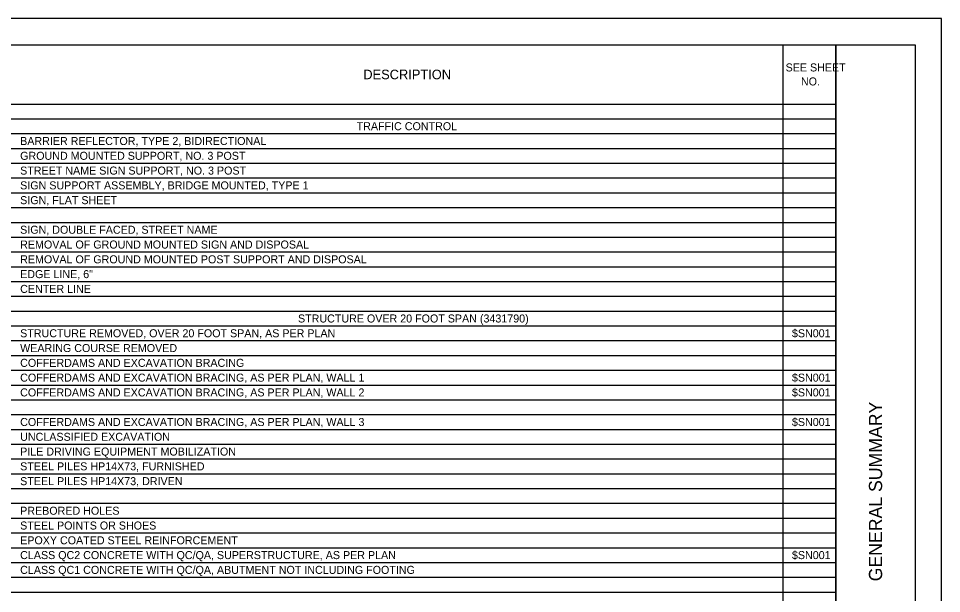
# Model space of a CAD drawing. Extents: x 0 to 34, y 0 to 22.
# Drawn here: x 16.52 to 34, y 11.11 to 22 of the extents above; entities that cross this region are included whole.
import ezdxf

# ---------------------------------------------------------------- set-up
doc = ezdxf.new("R2010")
doc.units = 0
for name, color, linetype in [('SH_Border', 7, 'Continuous'), ('SH_Cut_Line', 7, 'Continuous'), ('SH_Data', 7, 'Continuous'), ('SH_Text', 7, 'Continuous')]:
    doc.layers.add(name, color=color, linetype=linetype)

msp = doc.modelspace()

# ---------------------------------------------------------------- linework, layer by layer
at = {"layer": 'SH_Border'}
msp.add_line((32, 0.5), (32, 21.5), dxfattribs=at)
msp.add_lwpolyline([(1.5, 21.5), (33.5, 21.5), (33.5, 0.5), (1.5, 0.5)], close=True, dxfattribs=at)
at = {"layer": 'SH_Cut_Line'}
msp.add_lwpolyline([(0, 0), (34, 0), (34, 22), (0, 22)], close=True, dxfattribs=at)
at = {"layer": 'SH_Text'}
for p, q in [((1.5, 21.5), (32, 21.5)), ((30.995, 21.5), (30.995, 0.5)), ((32, 21.5), (32, 0.5)), ((1.5, 20.38), (32, 20.38)), ((1.5, 20.1), (32, 20.1)), ((1.5, 19.82), (32, 19.82)), ((1.5, 19.54), (32, 19.54)), ((1.5, 19.26), (32, 19.26)), ((1.5, 18.98), (32, 18.98)), ((1.5, 18.7), (32, 18.7)), ((1.5, 18.42), (32, 18.42)), ((1.5, 18.14), (32, 18.14)), ((1.5, 17.86), (32, 17.86)), ((1.5, 17.58), (32, 17.58)), ((1.5, 17.3), (32, 17.3)), ((1.5, 17.02), (32, 17.02)), ((1.5, 16.74), (32, 16.74)), ((1.5, 16.46), (32, 16.46)), ((1.5, 16.18), (32, 16.18)), ((1.5, 15.9), (32, 15.9)), ((1.5, 15.62), (32, 15.62)), ((1.5, 15.34), (32, 15.34)), ((1.5, 15.06), (32, 15.06)), ((1.5, 14.78), (32, 14.78)), ((1.5, 14.5), (32, 14.5)), ((1.5, 14.22), (32, 14.22)), ((1.5, 13.94), (32, 13.94)), ((1.5, 13.66), (32, 13.66)), ((1.5, 13.38), (32, 13.38)), ((1.5, 13.1), (32, 13.1)), ((1.5, 12.82), (32, 12.82)), ((1.5, 12.54), (32, 12.54)), ((1.5, 12.26), (32, 12.26)), ((1.5, 11.98), (32, 11.98)), ((1.5, 11.7), (32, 11.7)), ((1.5, 11.42), (32, 11.42)), ((1.5, 11.14), (32, 11.14))]:
    msp.add_line(p, q, dxfattribs=at)

# ---------------------------------------------------------------- texts
at = {"layer": 'SH_Data'}
msp.add_text('GENERAL SUMMARY', height=0.25, rotation=90, dxfattribs=at).set_placement((32.875, 11.344))
at = {"layer": 'SH_Text'}
for s, height, p in [('DESCRIPTION', 0.18184, (23.05, 20.849)), ('SEE SHEET ', 0.1515, (31.047, 20.997)), ('NO.', 0.1515, (31.338, 20.732)), ('TRAFFIC CONTROL', 0.15153, (22.924, 19.884)), ('BARRIER REFLECTOR, TYPE 2, BIDIRECTIONAL', 0.15153, (16.552, 19.604)), ('GROUND MOUNTED SUPPORT, NO. 3 POST', 0.15153, (16.552, 19.324)), ('STREET NAME SIGN SUPPORT, NO. 3 POST', 0.15153, (16.552, 19.044)), ('SIGN SUPPORT ASSEMBLY, BRIDGE MOUNTED, TYPE 1', 0.15153, (16.552, 18.764)), ('SIGN, FLAT SHEET', 0.15153, (16.552, 18.484)), ('SIGN, DOUBLE FACED, STREET NAME', 0.15153, (16.552, 17.924)), ('REMOVAL OF GROUND MOUNTED SIGN AND DISPOSAL', 0.15153, (16.552, 17.644)), ('REMOVAL OF GROUND MOUNTED POST SUPPORT AND DISPOSAL', 0.15153, (16.552, 17.364)), ('EDGE LINE, 6"', 0.15153, (16.552, 17.084)), ('CENTER LINE', 0.15153, (16.552, 16.804)), ('STRUCTURE OVER 20 FOOT SPAN (3431790)', 0.15153, (21.813, 16.244)), ('STRUCTURE REMOVED, OVER 20 FOOT SPAN, AS PER PLAN', 0.15153, (16.552, 15.964)), ('$SN001', 0.1515, (31.167, 15.964)), ('WEARING COURSE REMOVED', 0.15153, (16.552, 15.684)), ('COFFERDAMS AND EXCAVATION BRACING', 0.15153, (16.552, 15.404)), ('COFFERDAMS AND EXCAVATION BRACING, AS PER PLAN, WALL 1', 0.15153, (16.552, 15.124)), ('$SN001', 0.1515, (31.167, 15.124)), ('COFFERDAMS AND EXCAVATION BRACING, AS PER PLAN, WALL 2', 0.15153, (16.552, 14.844)), ('$SN001', 0.1515, (31.167, 14.844)), ('COFFERDAMS AND EXCAVATION BRACING, AS PER PLAN, WALL 3', 0.15153, (16.552, 14.284)), ('$SN001', 0.1515, (31.167, 14.284)), ('UNCLASSIFIED EXCAVATION', 0.15153, (16.552, 14.004)), ('PILE DRIVING EQUIPMENT MOBILIZATION', 0.15153, (16.552, 13.724)), ('STEEL PILES HP14X73, FURNISHED', 0.15153, (16.552, 13.444)), ('STEEL PILES HP14X73, DRIVEN', 0.15153, (16.552, 13.164)), ('PREBORED HOLES', 0.15153, (16.552, 12.604)), ('STEEL POINTS OR SHOES', 0.15153, (16.552, 12.324)), ('EPOXY COATED STEEL REINFORCEMENT', 0.15153, (16.552, 12.044)), ('CLASS QC2 CONCRETE WITH QC/QA, SUPERSTRUCTURE, AS PER PLAN', 0.15153, (16.552, 11.764)), ('$SN001', 0.1515, (31.167, 11.764)), ('CLASS QC1 CONCRETE WITH QC/QA, ABUTMENT NOT INCLUDING FOOTING', 0.15153, (16.552, 11.484))]:
    msp.add_text(s, height=height, dxfattribs=at).set_placement(p)

doc.saveas('drawing.dxf')
